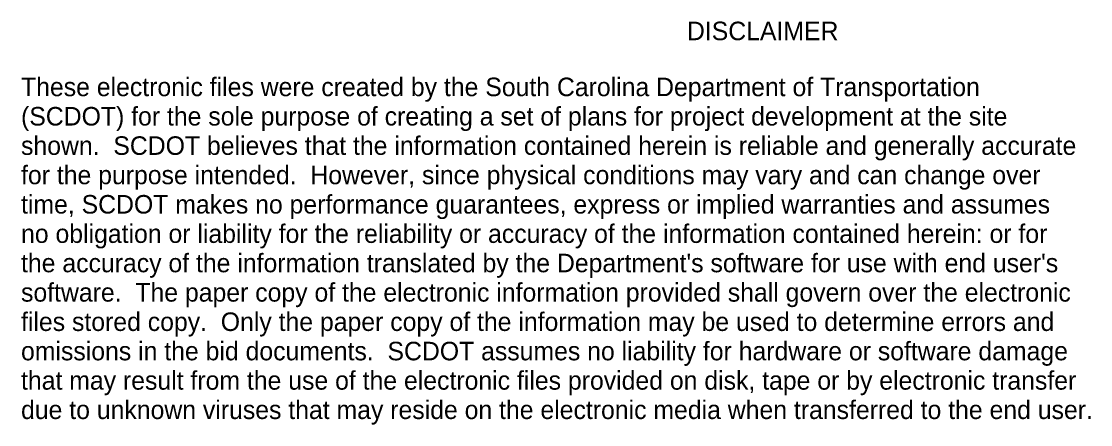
# Model space of a CAD drawing. Extents: x -4.82 to 4.15, y -0.44 to 2.32.
# Drawn here: x -3.929 to -2.931, y 1.943 to 2.32 of the extents above; entities that cross this region are included whole.
import ezdxf

# ---------------------------------------------------------------- set-up
doc = ezdxf.new("R2010")
doc.units = 0
doc.layers.add('BR_USER NOTES', color=7, linetype='Continuous')

msp = doc.modelspace()

# ---------------------------------------------------------------- texts
at = {"layer": 'BR_USER NOTES'}
for s, height, p in [('DISCLAIMER', 0.017305, (-3.30766, 2.30219)), ('These electronic files were created by the South Carolina Department of Transportation', 0.0173049, (-3.92941, 2.24994)), ('(SCDOT) for the sole purpose of creating a set of plans for project development at the site', 0.0173049, (-3.92941, 2.22254)), ('shown.  SCDOT believes that the information contained herein is reliable and generally accurate', 0.0173049, (-3.92941, 2.19513)), ('for the purpose intended.  However, since physical conditions may vary and can change over', 0.0173049, (-3.92941, 2.16773)), ('time, SCDOT makes no performance guarantees, express or implied warranties and assumes', 0.0173049, (-3.92941, 2.14033)), ('no obligation or liability for the reliability or accuracy of the information contained herein: or for', 0.01730492, (-3.92941, 2.11293)), ("the accuracy of the information translated by the Department's software for use with end user's", 0.0173049, (-3.92941, 2.08553)), ('software.  The paper copy of the electronic information provided shall govern over the electronic', 0.0173049, (-3.92941, 2.05812)), ('files stored copy.  Only the paper copy of the information may be used to determine errors and', 0.0173049, (-3.92941, 2.03072)), ('omissions in the bid documents.  SCDOT assumes no liability for hardware or software damage', 0.0173049, (-3.92941, 2.00332)), ('that may result from the use of the electronic files provided on disk, tape or by electronic transfer', 0.01730492, (-3.92941, 1.97592)), ('due to unknown viruses that may reside on the electronic media when transferred to the end user.', 0.0173049, (-3.92941, 1.94851))]:
    msp.add_text(s, height=height, rotation=360, dxfattribs=at).set_placement(p)

doc.saveas('drawing.dxf')
